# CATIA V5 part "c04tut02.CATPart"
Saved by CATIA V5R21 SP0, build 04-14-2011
Part number: c04tut02
Material "Aluminium": density 2710 kg/m3, Young's modulus 7e+10 Pa, Poisson ratio 0.346, thermal expansion 2.36e-05 1/K
Material "Aluminium": density 2710 kg/m3, Young's modulus 7e+10 Pa, Poisson ratio 0.346, thermal expansion 2.36e-05 1/K
Bounding box of the stored display mesh (mm): x 0 to 30, y -110 to 110, z -120 to 120
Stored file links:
  D:\CATIA V5R21 E-RESOURCES\CATIA-V5R21\catia-v5r21-prt\c04-catia-v5r20-prt\catia-v5r21-tut-02.CATPart
  C:\Program Files\Dassault Systemes\B21\win_b64\startup\materials\Catalog.CATMaterial
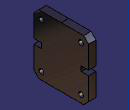
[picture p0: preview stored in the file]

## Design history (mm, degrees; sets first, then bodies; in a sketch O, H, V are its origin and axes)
Body1 (main body), material "Aluminium"
  Sketch1 on yz-plane, origin (0, 0, 0), H (0, 1, 0), V (0, 0, 1)
    construction line L1 (0, 0) -> (0, 117.7398)
    point P1 (0, 117.7398)
    axis line L2 (0, 0) -> (129.0807, 0)
    point P3 (0, 120)
    line L3 (0, 120) -> (90, 120)
    point P4 (90, 120)
    line L4 (90, 120) -> (110, 100)
    point P5 (110, 100)
    line L5 (110, 100) -> (110, 10)
    point P6 (110, 10)
    line L6 (110, 10) -> (80, 10)
    point P7 (80, 10)
    line L7 (80, 10) -> (80, 0)
    point P8 (80, 0)
    circle A1 centre (80, 90) radius 10
    point P9 (80, 90)
    point P10 (80, -10)
    point P11 (110, -10)
    line L8 (110, -10) -> (80, -10)
    point P12 (80, 0)
    line L9 (80, -10) -> (80, 0)
    point P13 (110, -100)
    line L10 (110, -100) -> (110, -10)
    circle A2 centre (80, -90) radius 10
    point P15 (90, -120)
    line L11 (90, -120) -> (110, -100)
    point P16 (0, -120)
    line L12 (0, -120) -> (90, -120)
    point P17 (0, -117.7398)
    point P18 (0, 0)
    construction line L13 (0, 0) -> (0, -117.7398)
    point P19 (-80, -10)
    point P20 (-110, -10)
    point P21 (-110, -100)
    point P23 (-90, -120)
    line L14 (-110, -10) -> (-80, -10)
    line L15 (-110, -100) -> (-110, -10)
    circle A3 centre (-80, -90) radius 10
    line L16 (-90, -120) -> (-110, -100)
    point P24 (0, -120)
    line L17 (0, -120) -> (-90, -120)
    point P25 (-80, 0)
    line L18 (-80, -10) -> (-80, 0)
    point P26 (-80, 0)
    point P27 (-80, 10)
    line L19 (-80, 10) -> (-80, 0)
    point P28 (-110, 10)
    line L20 (-110, 10) -> (-80, 10)
    point P29 (-110, 100)
    line L21 (-110, 100) -> (-110, 10)
    circle A4 centre (-80, 90) radius 10
    point P31 (-90, 120)
    line L22 (-90, 120) -> (-110, 100)
    point P32 (0, 120)
    line L23 (0, 120) -> (-90, 120)
    distance L15 L10 = 220
    distance L12 L3 = 240
    distance P9 L5 = 30
    distance P9 L3 = 30
    radius A1 = 10
    length L22 H = 20
    length L22 V = 20
    distance L8 L6 = 20
    distance L7 L19 = 160
    vertical: L1 V, L5 V, L7 V
    horizontal: L2 H, L3 H, L6 H
    coincidence: P3 L1, P8 L2, P3 P32, P8 P12, P16 P24, P25 P26
    symmetry: P7 P10 L2, P6 P11 L2, L6 L8 L2, P8 P12 L2, L7 L9 L2, P5 P13 L2, L5 L10 L2, A1 A2 L2, P4 P15 L2, L4 L11 L2, P3 P16 L2, L3 L12 L2, P1 P17 L2, O P18 L2, L1 L13 L2, P10 P19 L1, P11 P20 L1, P13 P21 L1, P15 P23 L1, L8 L14 L1, L10 L15 L1, A2 A3 L1, L11 L16 L1, P16 P24 L1, L12 L17 L1, P12 P25 L1, L9 L18 L1, P8 P26 L1, P7 P27 L1, L7 L19 L1, P6 P28 L1, L6 L20 L1, P5 P29 L1, L5 L21 L1, A1 A4 L1, P4 P31 L1, L4 L22 L1, P3 P32 L1, L3 L23 L1
  Pad1: profile Sketch1, direction (1, 0, 0), length 30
